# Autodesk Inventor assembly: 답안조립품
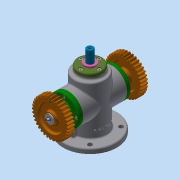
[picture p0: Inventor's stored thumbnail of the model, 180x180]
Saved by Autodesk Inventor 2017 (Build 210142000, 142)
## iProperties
Part Number: 답안조립품
Material: 일반
Document SubType Name: Assembly
Designer: mrc
Author: mrc
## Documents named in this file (17)
- C:\Users\mrc\Desktop\600606V1015\답안조립품.iam
- C:\Users\mrc\Desktop\600606V1015\본체.ipt
- C:\Users\mrc\Desktop\600606V1015\가변스프링.ipt
- C:\Users\mrc\Desktop\600606V1015\멈춤링.ipt
- C:\Users\mrc\Desktop\600606V1015\베어링 6203.ipt
- C:\Users\mrc\Desktop\600606V1015\볼트 M4.ipt
- C:\Users\mrc\Desktop\600606V1015\부시.ipt
- C:\Users\mrc\Desktop\600606V1015\스퍼기어.ipt
- C:\Users\mrc\Desktop\600606V1015\스프링와셔.ipt
- C:\Users\mrc\Desktop\600606V1015\스프링조립용 와셔.ipt
- C:\Users\mrc\Desktop\600606V1015\슬라이더.ipt
- C:\Users\mrc\Desktop\600606V1015\오일 실 17 30 8.ipt
- C:\Users\mrc\Desktop\600606V1015\커버 A.ipt
- C:\Users\mrc\Desktop\600606V1015\커버 B.ipt
- C:\Users\mrc\Desktop\600606V1015\키 4x4x12.ipt
- C:\Users\mrc\Desktop\600606V1015\편심축.ipt
- C:\Users\mrc\Desktop\600606V1015\평와셔.ipt
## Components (1 placed, 1 different names)
1. 가변스프링:1
